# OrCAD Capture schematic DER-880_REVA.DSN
size Custom; title: DER 880; rev: A
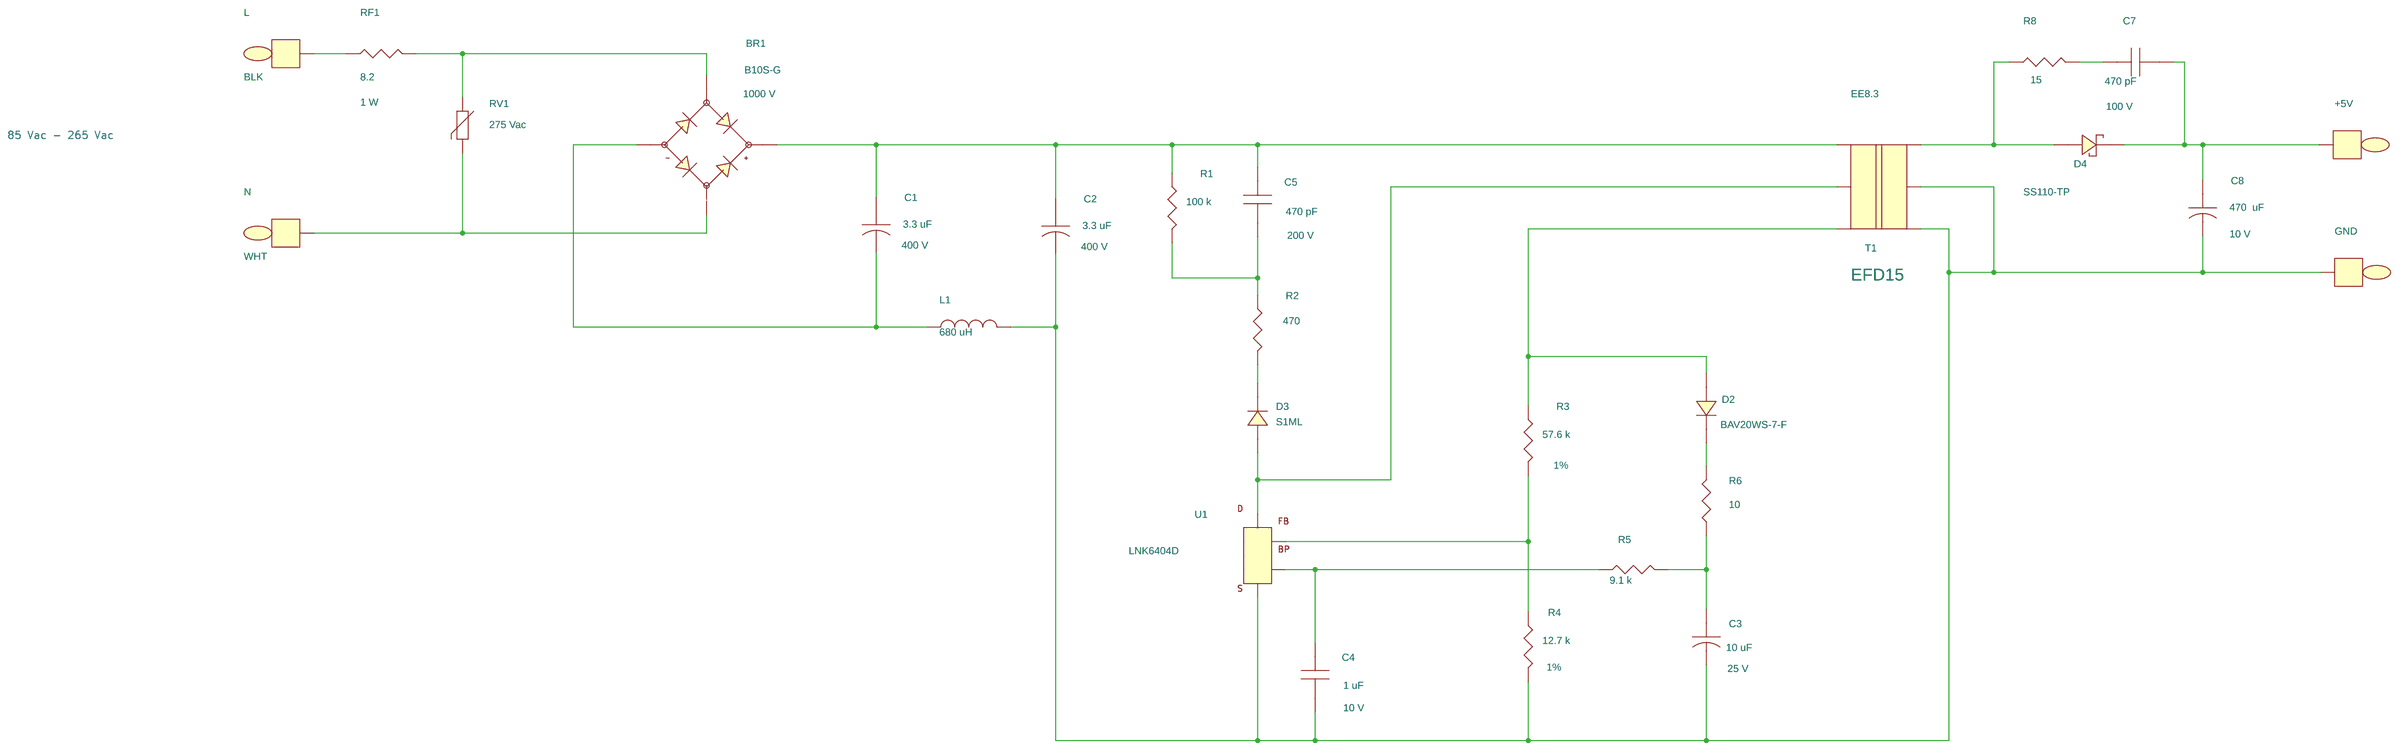
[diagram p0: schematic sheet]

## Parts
+5V  RED  [pitpkeystone100x100]
BR1  B10S-G  [pismsoic4]
C1  3.3 uF  [pipolcapclyd320ls140030]
C2  3.3 uF  [pipolcapclyd320ls140030]
C3  10 uF  [pipolcapclyd5mmls2mm025]
C4  1 uF  [pismc0805]
C5  470 pF  [pismc0805]
C7  470 pF  [pismc0805]
C8  470  uF  [pipolcapclyd320ls140030]
D2  BAV20WS-7-F  [pismdsod323]
D3  S1ML  [pi_sm_sod-123_12]
D4  SS110-TP  [pismdo214ac12]
GND  BLK  [pitpkeystone100x100]
L  BLK  [pitpkeystone100x100]
L1  680 uH  [pichoketokinvd216h413ls098d030]
N  WHT  [pitpkeystone100x100]
R1  100 k  [pismr0805]
R2  470  [pismr1206]
R3  57.6 k  [pismr0603]
R4  12.7 k  [pismr1206]
R5  9.1 k  [pismr0603]
R6  10  [pismr0603]
R8  15  [pismr0805]
RF1  8.2  [pi12wresd180ls575040]
RV1  275 Vac  [pi_disc276x181_ls200x83d040]
T1  EE8.3  [pi_bobbin_ee8_3H6p]
U1  LNK6404D  [pismso8dnshort5678]

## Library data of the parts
+5V = TESTPOINT: Part Number: 35-00080-00
BR1 = DIODE_BRIDGE_~~+-: ALT_SYMBOLS: pi_sm_soic4_slot; Disp_Voltage: 1000 V; FPLIST: pismsoic4,pi_sm_soic4_slot; Part Number: 15-00818-00
C1 C2 = CAP_POL: ALT_SYMBOLS: pipolcapclyd320ls140030430h; Disp_Voltage: 400 V; FPLIST: pipolcapclyd320ls140030,pipolcapclyd320ls140030430h,pipolcapclyd320ls140030430h; Part Number: 20-00593-00; Voltage: 400 V
C3 = CAP_POL: Disp_Voltage: 25 V; Part Number: 20-09124-00; Voltage: 25 V
C4 = CAP_NP: Disp_Voltage: 10 V; Part Number: 20-01455-00; Voltage: 10 V
C5 = CAP_NP: Disp_Voltage: 200 V; Part Number: 20-01187-00; Voltage: 200 V
C7 = CAP_NP: Disp_Voltage: 100 V; Part Number: 20-00905-00; Voltage: 100 V
C8 = CAP_POL: ALT_SYMBOLS: pipolcapclyd320ls140030430h; Disp_Voltage: 10 V; FPLIST: pipolcapclyd320ls140030,pipolcapclyd320ls140030430h; Part Number: 20-00003-00; Voltage: 10 V
D2 = DIODE: Part Number: 15-00712-00
D3 = DIODE: Part Number: 15-01027-00
D4 = DIODE_SCHOTTKY: Part Number: 15-00676-00
GND = TESTPOINT: Part Number: 35-00079-00
L = TESTPOINT: ALT_SYMBOLS: TP_TH_CR2_D1_1; FPLIST: pitpkeystone100x100,TP_TH_CR2_D1_1; Part Number: 35-00079-00
L1 = INDUCTOR: Part Number: 30-00019-00
N = TESTPOINT: Part Number: 35-00081-00
R1 = R: Part Number: 05-01567-00
R2 = R: Part Number: 05-01344-00
R3 = R: Disp_Tol: 1%; Part Number: 05-03257-00
R4 = R: Disp_Tol: 1%; Part Number: 05-00299-00
R5 = R: Part Number: 05-01711-00
R6 = R: Part Number: 05-01640-00
R8 = R: Part Number: 05-01475-00
RF1 = RF: ALT_SYMBOLS: pi1wvresd120ls200d040; Disp_Power: 1 W; FPLIST: pi12wresd180ls575040,pi1wvresd120ls200d040; Part Number: 05-06353-00
RV1 = VARISTOR: Part Number: 85-00040-00
T1 = BEE8_3_6P: Part Number: 25-01154-00
U1 = LNK6404: Part Number: 10-00655-00

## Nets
SOURCE: U1.6(SOURCE) U1.7(SOURCE) U1.8(SOURCE)
N02548: BR1.3 C1.1 C2.1 C5.1 R1.1 T1.3
N02674: BR1.4 C1.2 L1.1
N03502: C2.2 C3.2 C4.2 C8.2 GND.1 L1.2 R4.2 T1.5 T1.6 U1.5(S)
N03550: C4.1 R5.1 U1.2(BP)
N04036: R3.2 R4.1 U1.1(FB)
N04459: C3.1 R5.2 R6.1
N04496: D2.1 R6.2
N04748: D3.2 T1.2 U1.4(D)
N04766: D2.2 R3.1 T1.1
N04877: D4.2 R8.1 T1.4
N04912: C7.1 R8.2
N04991: +5V.1 C7.2 C8.1 D4.1
N06108: BR1.1 RF1.2 RV1.1
N06154: L.1 RF1.1
N06177: BR1.2 N.1 RV1.2
N12152: C5.2 R1.2 R2.1
N12184: D3.1 R2.2

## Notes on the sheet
- 85 Vac - 265 Vac
